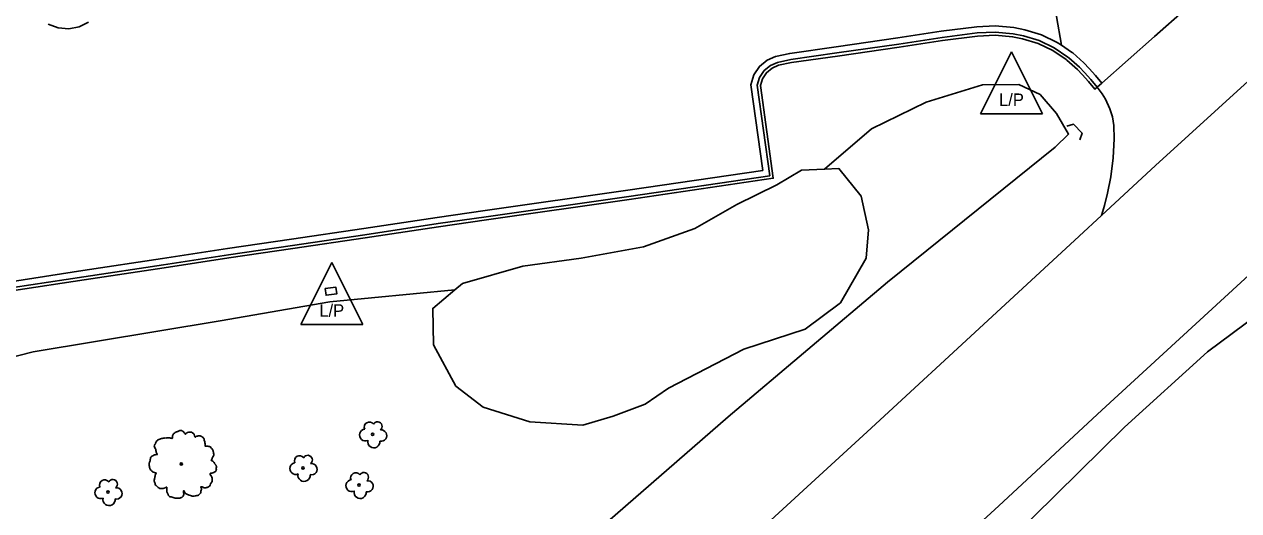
# Model space of a CAD drawing. Extents: x 2161152 to 2175754, y 602179 to 617749.
# Drawn here: x 2163537.9 to 2163733.9, y 606142.6 to 606221.2 of the extents above; entities that cross this region are included whole.
import ezdxf

# ---------------------------------------------------------------- set-up
doc = ezdxf.new("R2010")
doc.units = 0
for name, color, linetype in [('RD_EX_Conc_Curb', 7, 'Continuous'), ('RD_EX_Conc_Gutter', 7, 'Continuous'), ('RD_EX_DR_Pipe', 7, 'Continuous'), ('RD_EX_Parking_Asphalt', 7, 'Continuous'), ('RD_EX_Parking_Conc', 7, 'Continuous'), ('RD_EX_Road', 7, 'Continuous'), ('RD_EX_UT', 7, 'Continuous'), ('RD_EX_VEG', 7, 'Continuous')]:
    doc.layers.add(name, color=color, linetype=linetype)

msp = doc.modelspace()

# ---------------------------------------------------------------- linework, layer by layer
at = {"layer": 'RD_EX_Conc_Curb'}
for points in [[(2163536.15, 606178.68), (2163547.52, 606180.43), (2163560.4, 606182.37), (2163570.89, 606183.97), (2163581.21, 606185.49), (2163592.86, 606187.21), (2163604.7, 606189), (2163612.45, 606190.12), (2163635.48, 606193.4), (2163658.23, 606196.74), (2163656.22, 606211.33), (2163656.59, 606212.6), (2163657.32, 606213.71), (2163658.34, 606214.55), (2163659.48, 606215.04), (2163661.64, 606215.5), (2163669.09, 606216.55), (2163679.08, 606218), (2163686.04, 606219.06), (2163691.73, 606219.78), (2163694.62, 606219.92), (2163697.5, 606219.66), (2163699.17, 606219.33), (2163701.73, 606218.54), (2163704.15, 606217.39), (2163706.37, 606215.89), (2163706.5, 606215.79), (2163708.25, 606214.25), (2163709.03, 606213.38), (2163710.04, 606212.25), (2163711.1, 606211.03)], [(2163711.1, 606211.03), (2163711.1, 606211.03), (2163710.72, 606210.7), (2163709.67, 606211.92), (2163708.66, 606213.05), (2163707.9, 606213.9), (2163706.18, 606215.4), (2163706.08, 606215.48), (2163703.9, 606216.95), (2163701.55, 606218.08), (2163699.04, 606218.85), (2163697.43, 606219.17), (2163694.61, 606219.42), (2163691.77, 606219.28), (2163686.11, 606218.57), (2163679.15, 606217.51), (2163669.16, 606216.06), (2163661.73, 606215.01), (2163659.63, 606214.56), (2163658.61, 606214.12), (2163657.7, 606213.37), (2163657.05, 606212.39), (2163656.73, 606211.29), (2163658.8, 606196.32), (2163635.55, 606192.9), (2163612.52, 606189.62), (2163604.77, 606188.5), (2163592.93, 606186.72), (2163581.28, 606185), (2163570.96, 606183.48), (2163560.48, 606181.88), (2163547.59, 606179.94), (2163536.22, 606178.19)]]:
    msp.add_lwpolyline(points, dxfattribs=at)
at = {"layer": 'RD_EX_Conc_Gutter'}
for points in [[(2163548.29, 606221.52), (2163546.76, 606220.76), (2163545.09, 606220.44), (2163543.39, 606220.59), (2163541.8, 606221.2)], [(2163711.1, 606211.03), (2163711.86, 606211.68), (2163710.79, 606212.92), (2163709.77, 606214.05), (2163708.95, 606214.96), (2163707.14, 606216.56), (2163706.96, 606216.69), (2163705.32, 606217.8), (2163704.65, 606218.26), (2163702.1, 606219.48), (2163699.41, 606220.31), (2163697.64, 606220.66), (2163694.64, 606220.92), (2163691.64, 606220.77), (2163685.9, 606220.05), (2163678.93, 606218.99), (2163668.95, 606217.54), (2163661.47, 606216.48), (2163659.18, 606215.99), (2163657.82, 606215.41), (2163656.57, 606214.38), (2163655.68, 606213.03), (2163655.2, 606211.41), (2163657.11, 606197.59), (2163635.34, 606194.39), (2163612.3, 606191.11), (2163604.55, 606189.98), (2163592.71, 606188.2), (2163581.06, 606186.48), (2163570.74, 606184.96), (2163560.25, 606183.36), (2163547.37, 606181.42), (2163536, 606179.67)]]:
    msp.add_lwpolyline(points, dxfattribs=at)
at = {"layer": 'RD_EX_DR_Pipe'}
msp.add_lwpolyline([(2163708.26, 606202.54), (2163708.64, 606203.58), (2163707.27, 606205.04), (2163706.2, 606204.72)], dxfattribs=at)
at = {"layer": 'RD_EX_Parking_Asphalt'}
msp.add_lwpolyline([(2163711.1, 606211.03), (2163711.88, 606209.95), (2163712.41, 606209.08), (2163713.14, 606207.55), (2163713.54, 606206.24), (2163713.78, 606204.82), (2163713.85, 606202.71), (2163713.67, 606199.63), (2163713.27, 606196.55), (2163712.73, 606193.91), (2163712.24, 606191.91), (2163711.78, 606190.3)], dxfattribs=at)
at = {"layer": 'RD_EX_Parking_Conc'}
for points in [[(2163705.32, 606217.8), (2163704.53, 606222.46), (2163703.51, 606227.84), (2163702.4, 606234.46), (2163700.51, 606244.88), (2163699.75, 606249.93), (2163697.86, 606261.87)], [(2163730.34, 606228.09), (2163720.34, 606219.23), (2163711.86, 606211.68)]]:
    msp.add_lwpolyline(points, dxfattribs=at)
at = {"layer": 'RD_EX_Road'}
for points in [[(2163875.41, 606341.16), (2163843.65, 606312.1), (2163821.47, 606291.55), (2163800.55, 606272.14), (2163780.74, 606253.92), (2163769.08, 606243.22), (2163753.16, 606228.62), (2163752.68, 606228.18), (2163736.03, 606212.55), (2163720.51, 606198.38), (2163711.78, 606190.3), (2163708.15, 606186.95), (2163694.14, 606174.02), (2163673.96, 606155.38), (2163651.97, 606135.18), (2163628.42, 606113.37), (2163602.14, 606089.14), (2163584.89, 606073.34), (2163567.66, 606057.41), (2163543.67, 606035.28), (2163521.89, 606015.12)], [(2163449.16, 605916.57), (2163480.7, 605945.66), (2163507.12, 605970.04), (2163519.49, 605981.54), (2163538.78, 605999.59), (2163549.3, 606009.29), (2163566.47, 606025.19), (2163585.52, 606042.74), (2163604.13, 606059.76), (2163621.17, 606075.39), (2163643.67, 606096.22), (2163665.02, 606115.84), (2163683.11, 606132.37), (2163695.21, 606143.44), (2163711.83, 606158.88), (2163734.25, 606179.52), (2163756.74, 606200.15), (2163775.1, 606217.09), (2163795.1, 606235.76), (2163814.8, 606253.97), (2163835.17, 606272.79), (2163857.2, 606292.93), (2163879.81, 606313.76)]]:
    msp.add_lwpolyline(points, dxfattribs=at)
at = {"layer": 'RD_EX_UT'}
for p, q in [((2163692.25, 606206.73), (2163697.25, 606216.73)), ((2163697.25, 606216.73), (2163702.25, 606206.73)), ((2163692.25, 606206.73), (2163702.25, 606206.73)), ((2163582.55, 606172.7), (2163587.55, 606182.7)), ((2163587.55, 606182.7), (2163592.55, 606172.7)), ((2163582.55, 606172.7), (2163592.55, 606172.7))]:
    msp.add_line(p, q, dxfattribs=at)
msp.add_lwpolyline([(2163586.48, 606178.52), (2163588.23, 606178.74), (2163588.36, 606177.66), (2163586.62, 606177.44), (2163586.48, 606178.52)], dxfattribs=at)
at = {"layer": 'RD_EX_VEG'}
for points in [[(2163522.51, 605974.72), (2163543.42, 605992.52), (2163564.29, 606011.65), (2163582.91, 606029.48), (2163594.9, 606041.15), (2163615.08, 606061.96), (2163628.18, 606075.57), (2163646.78, 606090.38), (2163665.44, 606105.76), (2163682.04, 606123.5), (2163700.82, 606141.64), (2163715.5, 606156.13), (2163728.9, 606168.3), (2163745.01, 606180.31), (2163758.6, 606192.2), (2163779.21, 606213.19), (2163799.99, 606233.36), (2163817.63, 606249.82), (2163835.67, 606266.65), (2163848.26, 606279.19), (2163864.81, 606294.08), (2163881.27, 606308.75)], [(2163667.08, 606197.79), (2163674.65, 606204.31), (2163683.47, 606208.59), (2163692.59, 606211.41), (2163698.46, 606211.45), (2163701.86, 606209.83), (2163704.51, 606206.79), (2163706.47, 606203.47), (2163704.28, 606201.36), (2163677.22, 606179.57), (2163651.52, 606157.82), (2163630.83, 606139.77), (2163621.47, 606133.37), (2163610.8, 606128.26), (2163593.45, 606123.53), (2163578.85, 606118.89), (2163571.11, 606113.12), (2163564.5, 606106.67), (2163561.21, 606102.4), (2163556.44, 606092.56), (2163547.75, 606080.36), (2163540.36, 606073.06), (2163534.71, 606066.99)], [(2163641.92, 606162.45), (2163638.15, 606159.84), (2163632.95, 606157.91), (2163628.08, 606156.47), (2163619.49, 606156.98), (2163611.97, 606159.35), (2163607.59, 606162.77), (2163603.97, 606169.45), (2163603.85, 606175.31), (2163607.39, 606178.3), (2163608.63, 606179.36), (2163618.4, 606182.13), (2163627.79, 606183.4), (2163637.86, 606185.26), (2163646.15, 606188.22), (2163652.91, 606192.11), (2163659.39, 606195.24), (2163663.35, 606197.62), (2163667.08, 606197.79), (2163669.39, 606197.9), (2163672.98, 606193.44), (2163674.17, 606187.99), (2163673.8, 606183.44), (2163669.64, 606176.22), (2163663.98, 606171.98), (2163654.05, 606168.74), (2163641.92, 606162.45)], [(2163464.1, 606036.47), (2163466.48, 606048.95), (2163469.97, 606060.12), (2163470.53, 606068.2), (2163469.36, 606073.82), (2163471.01, 606086.68), (2163477.33, 606115.89), (2163479.93, 606120.79), (2163483.77, 606125.42), (2163485.45, 606127.46), (2163487.67, 606130.86), (2163490.06, 606134.65), (2163492.05, 606137.09), (2163495.42, 606140.53), (2163505.05, 606150.13), (2163515.84, 606159.28), (2163520.91, 606162.37), (2163527.28, 606165.21), (2163539.36, 606168.29), (2163569.55, 606173.33), (2163587.23, 606176.36), (2163607.39, 606178.3)]]:
    msp.add_lwpolyline(points, dxfattribs=at)
for centre, radius in [((2163594.14, 606154.99), 0.188), ((2163563.27, 606150.21), 0.188), ((2163563.26, 606150.2), 0.000075), ((2163582.89, 606149.57), 0.188), ((2163591.95, 606146.8), 0.188), ((2163551.42, 606145.66), 0.188)]:
    msp.add_circle(centre, radius, dxfattribs=at)
for centre, radius, start, end in [((2163593.6, 606156.15), 0.813, 34.9763, 204.756), ((2163594.93, 606156.26), 0.746, 308.7626, 152.0467), ((2163592.97, 606154.87), 0.943, 96.4518, 294.734), ((2163595.52, 606154.78), 0.914, 256.5667, 98.1046), ((2163594.33, 606153.79), 0.988, 166.8827, 5.7589), ((2163582.35, 606150.73), 0.813, 34.9763, 204.756), ((2163583.68, 606150.85), 0.746, 308.7626, 152.0467), ((2163581.72, 606149.45), 0.943, 96.4518, 294.734), ((2163583.08, 606148.37), 0.988, 166.8827, 5.7589), ((2163584.27, 606149.36), 0.914, 256.5667, 98.1046), ((2163591.41, 606147.96), 0.813, 34.9763, 204.756), ((2163592.73, 606148.08), 0.746, 308.7626, 152.0467), ((2163550.88, 606146.82), 0.813, 34.9763, 204.756), ((2163552.21, 606146.94), 0.746, 308.7626, 152.0467), ((2163590.77, 606146.69), 0.943, 96.4518, 294.734), ((2163593.33, 606146.59), 0.914, 256.5667, 98.1046), ((2163550.25, 606145.55), 0.943, 96.4518, 294.734), ((2163551.61, 606144.47), 0.988, 166.8827, 5.7589), ((2163552.8, 606145.45), 0.914, 256.5667, 98.1046), ((2163592.13, 606145.61), 0.988, 166.8827, 5.7589)]:
    msp.add_arc(centre, radius, start, end, dxfattribs=at)
for points in [[(2163563.37, 606155.59), (2163563.15, 606155.6), (2163562.9, 606155.53), (2163562.71, 606155.45), (2163562.55, 606155.4), (2163562.38, 606155.32), (2163562.15, 606155.19), (2163561.98, 606155.04), (2163561.89, 606154.85), (2163561.85, 606154.69), (2163561.82, 606154.48), (2163561.82, 606154.35), (2163561.72, 606154.33), (2163561.61, 606154.35), (2163561.42, 606154.4), (2163561.23, 606154.4), (2163561.05, 606154.4), (2163560.78, 606154.39), (2163560.52, 606154.39), (2163560.32, 606154.35), (2163560.07, 606154.31), (2163559.79, 606154.22), (2163559.53, 606154.12), (2163559.3, 606153.94), (2163559.12, 606153.58), (2163559.02, 606153.32), (2163558.91, 606153.13), (2163559.02, 606152.79), (2163559.15, 606152.53), (2163559.17, 606152.38), (2163559.23, 606152.06), (2163559.3, 606151.89), (2163559.4, 606151.74), (2163559.34, 606151.72), (2163559.06, 606151.69), (2163558.84, 606151.61), (2163558.52, 606151.44), (2163558.35, 606151.27), (2163558.27, 606151.03), (2163558.25, 606150.77), (2163558.18, 606150.62), (2163558.12, 606150.41), (2163558.1, 606150.36), (2163558.07, 606150.11), (2163558.14, 606149.78), (2163558.16, 606149.51), (2163558.25, 606149.34), (2163558.37, 606149.21), (2163558.5, 606149.03), (2163558.8, 606148.86), (2163559.04, 606148.78), (2163559.19, 606148.76), (2163559.06, 606148.39), (2163559.02, 606148.13), (2163558.93, 606147.83), (2163558.93, 606147.77), (2163558.89, 606147.41), (2163559, 606147.17), (2163559.06, 606146.89), (2163559.19, 606146.72), (2163559.4, 606146.5), (2163559.64, 606146.33), (2163560.02, 606146.23), (2163560.32, 606146.25), (2163560.75, 606146.38), (2163560.93, 606146.44), (2163560.92, 606146.31), (2163560.93, 606146.03), (2163560.93, 606145.71), (2163561.05, 606145.46), (2163561.12, 606145.26), (2163561.23, 606145.07), (2163561.48, 606144.9), (2163561.78, 606144.85), (2163562.1, 606144.73), (2163562.43, 606144.68), (2163562.81, 606144.66), (2163563.26, 606144.77), (2163563.46, 606144.87), (2163563.54, 606145), (2163563.69, 606145.28), (2163563.65, 606145.45), (2163563.67, 606145.9), (2163563.75, 606145.76), (2163563.88, 606145.5), (2163564.25, 606145.28), (2163564.55, 606145.15), (2163564.91, 606145.03), (2163565.13, 606144.98), (2163565.49, 606145.03), (2163565.77, 606145.09), (2163566.05, 606145.18), (2163566.28, 606145.39), (2163566.41, 606145.6), (2163566.44, 606145.8), (2163566.5, 606146.08), (2163566.54, 606146.21)], [(2163566.54, 606146.21), (2163566.48, 606146.35), (2163566.44, 606146.53), (2163566.5, 606146.51), (2163566.63, 606146.48), (2163566.84, 606146.38), (2163567.01, 606146.33), (2163567.25, 606146.35), (2163567.46, 606146.42), (2163567.79, 606146.63), (2163568, 606146.98), (2163568.21, 606147.28), (2163568.26, 606147.53), (2163568.22, 606147.7), (2163568.21, 606148.07), (2163568.06, 606148.26), (2163568.02, 606148.35), (2163567.94, 606148.65), (2163568, 606148.69), (2163568.21, 606148.73), (2163568.49, 606148.82), (2163568.69, 606148.91), (2163568.86, 606149.04), (2163568.92, 606149.21), (2163568.9, 606149.51), (2163568.94, 606149.81), (2163568.88, 606149.93), (2163568.81, 606150.04), (2163568.75, 606150.19), (2163568.64, 606150.3), (2163568.56, 606150.41), (2163568.49, 606150.49), (2163568.39, 606150.6), (2163568.26, 606150.69), (2163568.15, 606150.73), (2163568.11, 606150.84), (2163568.22, 606150.99), (2163568.26, 606151.07), (2163568.28, 606151.24), (2163568.45, 606151.5), (2163568.49, 606151.8), (2163568.45, 606152.12), (2163568.41, 606152.32), (2163568.3, 606152.53), (2163568.15, 606152.72), (2163568.06, 606152.85), (2163567.92, 606152.94), (2163567.68, 606153.04), (2163567.49, 606153.07), (2163567.23, 606153.07), (2163567.08, 606153.11), (2163567.1, 606153.15), (2163567.1, 606153.26), (2163567.1, 606153.47), (2163567.04, 606153.8), (2163566.93, 606154.18), (2163566.93, 606154.2), (2163566.86, 606154.39), (2163566.69, 606154.54), (2163566.56, 606154.61), (2163566.41, 606154.7), (2163566.22, 606154.72), (2163565.99, 606154.72), (2163565.79, 606154.69), (2163565.64, 606154.61), (2163565.51, 606154.52), (2163565.45, 606154.63), (2163565.38, 606154.85), (2163565.34, 606154.97), (2163565.23, 606155.1), (2163565.06, 606155.25), (2163564.72, 606155.34), (2163564.25, 606155.29), (2163564.03, 606155.14), (2163563.91, 606155), (2163563.88, 606155.1), (2163563.73, 606155.25), (2163563.65, 606155.38), (2163563.52, 606155.47), (2163563.41, 606155.55), (2163563.33, 606155.59)]]:
    msp.add_spline(points, degree=3, dxfattribs=at)

# ---------------------------------------------------------------- texts
at = {"layer": 'RD_EX_UT'}
for p in [(2163695.24, 606208.01), (2163585.54, 606173.98)]:
    msp.add_text('L/P', height=2, dxfattribs=at).set_placement(p)

doc.saveas('drawing.dxf')
